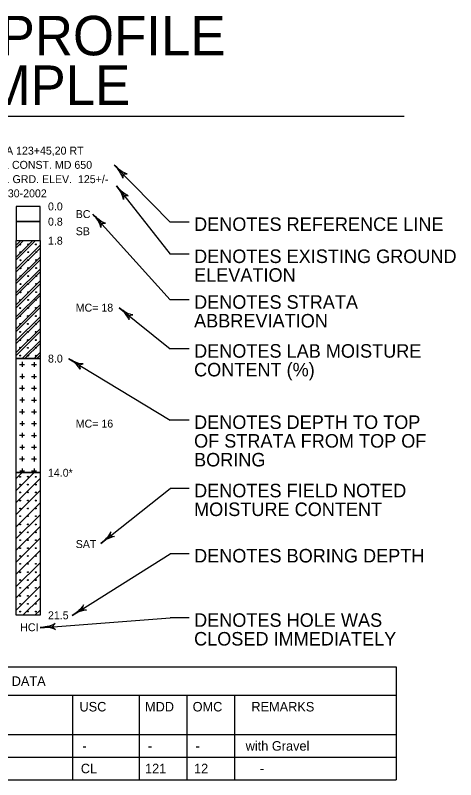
# Model space of a CAD drawing. Extents: x 1.3 to 42.5, y 0 to 21.2.
# Drawn here: x 23.44 to 27.34, y 5.49 to 12.28 of the extents above; entities that cross this region are included whole.
import ezdxf

# ---------------------------------------------------------------- set-up
doc = ezdxf.new("R2010")
doc.units = 0
doc.layers.add('SOIL-BORE', color=7, linetype='Continuous')

msp = doc.modelspace()

# ---------------------------------------------------------------- linework, layer by layer
at = {"layer": 'SOIL-BORE'}
for p, q in [((19.6501, 11.3816), (26.8821, 11.3816)), ((24.3133, 10.9467), (24.8097, 10.4403)), ((24.3135, 10.9469), (24.3135, 10.9469)), ((24.3891, 10.8697), (24.3135, 10.9469)), ((24.3323, 10.9257), (24.3135, 10.9469)), ((24.3351, 10.9265), (24.3135, 10.9469)), ((24.3437, 10.9141), (24.3323, 10.9257)), ((24.3465, 10.9169), (24.3351, 10.9265)), ((24.3577, 10.8957), (24.3437, 10.9141)), ((24.3597, 10.9053), (24.3465, 10.9169)), ((24.3699, 10.8755), (24.3577, 10.8957)), ((24.3701, 10.8967), (24.3597, 10.9053)), ((24.3801, 10.8555), (24.3699, 10.8755)), ((24.3901, 10.8839), (24.3701, 10.8967)), ((24.3859, 10.8421), (24.3801, 10.8555)), ((24.3891, 10.8697), (24.3885, 10.8315)), ((24.3891, 10.8697), (24.4271, 10.8693)), ((24.4045, 10.8771), (24.3901, 10.8839)), ((24.4167, 10.8723), (24.4045, 10.8771)), ((24.4271, 10.8693), (24.4167, 10.8723)), ((24.3885, 10.8315), (24.3859, 10.8421)), ((24.3319, 10.7635), (24.8098, 10.1561)), ((24.3321, 10.7637), (24.3321, 10.7637)), ((24.3989, 10.6787), (24.3321, 10.7637)), ((24.3485, 10.7405), (24.3321, 10.7637)), ((24.3515, 10.7411), (24.3321, 10.7637)), ((24.3585, 10.7279), (24.3485, 10.7405)), ((24.3615, 10.7303), (24.3515, 10.7411)), ((24.3705, 10.7081), (24.3585, 10.7279)), ((24.3737, 10.7173), (24.3615, 10.7303)), ((24.3829, 10.7077), (24.3737, 10.7173)), ((24.3805, 10.6869), (24.3705, 10.7081)), ((24.3885, 10.6655), (24.3805, 10.6869)), ((24.4015, 10.6931), (24.3829, 10.7077)), ((24.3927, 10.6517), (24.3885, 10.6655)), ((24.3943, 10.6409), (24.3927, 10.6517)), ((24.3989, 10.6787), (24.3943, 10.6409)), ((24.3989, 10.6787), (24.4367, 10.6743)), ((24.4147, 10.6847), (24.4015, 10.6931)), ((24.4267, 10.6785), (24.4147, 10.6847)), ((24.4367, 10.6743), (24.4267, 10.6785)), ((24.1239, 10.5119), (24.1239, 10.5119)), ((24.1963, 10.4317), (24.1239, 10.5119)), ((24.1421, 10.4899), (24.1239, 10.5119)), ((24.1451, 10.4907), (24.1239, 10.5119)), ((24.1239, 10.5118), (24.8098, 9.75)), ((24.1529, 10.4779), (24.1421, 10.4899)), ((24.1559, 10.4805), (24.1451, 10.4907)), ((24.1663, 10.4589), (24.1529, 10.4779)), ((24.1685, 10.4683), (24.1559, 10.4805)), ((24.1777, 10.4385), (24.1663, 10.4589)), ((24.1787, 10.4595), (24.1685, 10.4683)), ((24.1979, 10.4459), (24.1787, 10.4595)), ((24.2119, 10.4385), (24.1979, 10.4459)), ((24.1871, 10.4179), (24.1777, 10.4385)), ((24.1919, 10.4041), (24.1871, 10.4179)), ((24.1945, 10.3935), (24.1919, 10.4041)), ((24.1963, 10.4317), (24.1945, 10.3935)), ((24.1963, 10.4317), (24.2343, 10.4297)), ((24.2241, 10.4331), (24.2119, 10.4385)), ((24.2343, 10.4297), (24.2241, 10.4331)), ((24.9785, 10.4403), (24.8098, 10.4403)), ((23.5075, 10.276), (23.4439, 10.2124)), ((23.4842, 10.276), (23.4439, 10.2357)), ((23.591, 10.276), (23.4439, 10.1288)), ((23.6157, 10.276), (23.4439, 10.1042)), ((23.6549, 10.2357), (23.4439, 10.0247)), ((23.6549, 10.2097), (23.4439, 9.9987)), ((23.6549, 10.1289), (23.4439, 9.9179)), ((24.9785, 10.1561), (24.8098, 10.1561)), ((23.6549, 10.1056), (23.4439, 9.8946)), ((23.6549, 10.022), (23.4446, 9.8117)), ((23.6549, 10.0001), (23.446, 9.7911)), ((23.6549, 9.9179), (23.4439, 9.7069)), ((23.6549, 9.8919), (23.4439, 9.6808)), ((23.6549, 9.811), (23.4439, 9.6)), ((23.6549, 9.7877), (23.4439, 9.5767)), ((23.6549, 9.7055), (23.4439, 9.4945)), ((24.9785, 9.75), (24.8098, 9.75)), ((23.6549, 9.6822), (23.4439, 9.4712)), ((24.3553, 9.6803), (24.3553, 9.6803)), ((24.4399, 9.6127), (24.3553, 9.6803)), ((24.3767, 9.6617), (24.3553, 9.6803)), ((24.3793, 9.6627), (24.3553, 9.6803)), ((24.3553, 9.6802), (24.8098, 9.3161)), ((24.3893, 9.6513), (24.3767, 9.6617)), ((24.3917, 9.6547), (24.3793, 9.6627)), ((24.4055, 9.6349), (24.3893, 9.6513)), ((24.4063, 9.6447), (24.3917, 9.6547)), ((24.4201, 9.6165), (24.4055, 9.6349)), ((24.4177, 9.6373), (24.4063, 9.6447)), ((24.4391, 9.6271), (24.4177, 9.6373)), ((23.6549, 9.6), (23.4439, 9.389)), ((23.6549, 9.574), (23.4439, 9.363)), ((24.4329, 9.5977), (24.4201, 9.6165)), ((24.4399, 9.5849), (24.4329, 9.5977)), ((24.4541, 9.6223), (24.4391, 9.6271)), ((24.4399, 9.6127), (24.4777, 9.6171)), ((24.4399, 9.6127), (24.4439, 9.5749)), ((24.4439, 9.5749), (24.4399, 9.5849)), ((24.4669, 9.6187), (24.4541, 9.6223)), ((24.4777, 9.6171), (24.4669, 9.6187)), ((23.6549, 9.4932), (23.4439, 9.2822)), ((23.6549, 9.4685), (23.4439, 9.2575)), ((23.6549, 9.3877), (23.497, 9.2297)), ((23.6549, 9.3644), (23.5203, 9.2297)), ((24.9785, 9.3161), (24.8098, 9.3161)), ((23.6549, 9.2822), (23.6025, 9.2297)), ((23.6549, 9.2589), (23.6257, 9.2297)), ((23.909, 9.2284), (24.8098, 8.684)), ((23.9091, 9.2285), (23.9091, 9.2285)), ((24.0017, 9.1727), (23.9091, 9.2285)), ((23.9327, 9.2129), (23.9091, 9.2285)), ((23.9353, 9.2145), (23.9091, 9.2285)), ((23.4739, 9.1772), (23.5167, 9.1772)), ((23.4953, 9.1983), (23.4953, 9.1561)), ((23.496, 9.1991), (23.496, 9.1569)), ((23.5808, 9.1765), (23.6237, 9.1765)), ((23.6022, 9.1976), (23.6022, 9.1554)), ((23.9465, 9.2045), (23.9327, 9.2129)), ((23.9487, 9.2077), (23.9353, 9.2145)), ((23.9649, 9.1903), (23.9465, 9.2045)), ((23.9643, 9.1999), (23.9487, 9.2077)), ((23.9765, 9.1939), (23.9643, 9.1999)), ((23.9817, 9.1737), (23.9649, 9.1903)), ((23.9989, 9.1869), (23.9765, 9.1939)), ((23.9965, 9.1567), (23.9817, 9.1737)), ((24.0147, 9.1837), (23.9989, 9.1869)), ((24.0017, 9.1727), (24.0387, 9.1819)), ((24.0017, 9.1727), (24.0109, 9.1357)), ((24.0279, 9.1821), (24.0147, 9.1837)), ((24.0387, 9.1819), (24.0279, 9.1821)), ((23.4968, 9.0928), (23.4968, 9.0506)), ((23.6022, 9.0921), (23.6022, 9.0499)), ((24.0055, 9.1451), (23.9965, 9.1567)), ((24.0109, 9.1357), (24.0055, 9.1451)), ((23.4754, 9.0717), (23.5182, 9.0717)), ((23.5808, 9.071), (23.6237, 9.071)), ((23.4739, 8.9678), (23.5167, 8.9678)), ((23.4953, 8.9889), (23.4953, 8.9467)), ((23.496, 8.9896), (23.496, 8.9474)), ((23.5808, 8.967), (23.6237, 8.967)), ((23.6022, 8.9881), (23.6022, 8.9459)), ((23.4754, 8.8623), (23.5182, 8.8623)), ((23.4968, 8.8834), (23.4968, 8.8412)), ((23.5808, 8.8616), (23.6237, 8.8616)), ((23.6022, 8.8827), (23.6022, 8.8405)), ((23.4739, 8.7583), (23.5167, 8.7583)), ((23.4953, 8.7794), (23.4953, 8.7372)), ((23.496, 8.7802), (23.496, 8.738)), ((23.5808, 8.7576), (23.6237, 8.7576)), ((23.6022, 8.7787), (23.6022, 8.7365)), ((24.9785, 8.684), (24.8098, 8.684)), ((23.4754, 8.6529), (23.5182, 8.6529)), ((23.4968, 8.674), (23.4968, 8.6318)), ((23.5808, 8.6521), (23.6237, 8.6521)), ((23.6022, 8.6732), (23.6022, 8.631)), ((23.4739, 8.5489), (23.5167, 8.5489)), ((23.4953, 8.57), (23.4953, 8.5278)), ((23.496, 8.5707), (23.496, 8.5285)), ((23.5808, 8.5481), (23.6237, 8.5481)), ((23.6022, 8.5692), (23.6022, 8.527)), ((23.4754, 8.4434), (23.5182, 8.4434)), ((23.4968, 8.4645), (23.4968, 8.4223)), ((23.5808, 8.4427), (23.6237, 8.4427)), ((23.6022, 8.4638), (23.6022, 8.4216)), ((23.4953, 8.3606), (23.4953, 8.3184)), ((23.496, 8.3613), (23.496, 8.3191)), ((23.6022, 8.3598), (23.6022, 8.3176)), ((23.4739, 8.3395), (23.5167, 8.3395)), ((23.5808, 8.3387), (23.6237, 8.3387)), ((23.4439, 8.0585), (23.6026, 8.2172)), ((23.4439, 8.165), (23.4962, 8.2172)), ((23.4754, 8.234), (23.5182, 8.234)), ((23.4968, 8.2551), (23.4968, 8.2129)), ((23.5808, 8.2332), (23.6237, 8.2332)), ((23.6022, 8.2543), (23.6022, 8.2121)), ((23.4439, 7.953), (23.6549, 8.164)), ((24.193, 7.588), (24.8098, 8.0767)), ((24.9785, 8.0767), (24.8098, 8.0767)), ((23.4439, 7.8465), (23.6549, 8.0575)), ((23.4439, 7.7379), (23.6549, 7.9489)), ((23.4439, 7.6334), (23.6549, 7.8444)), ((23.4439, 7.5289), (23.6549, 7.7399)), ((24.2719, 7.6711), (24.2635, 7.6577)), ((24.2781, 7.6831), (24.2719, 7.6711)), ((24.2779, 7.6553), (24.2821, 7.6931)), ((24.2821, 7.6931), (24.2781, 7.6831)), ((23.4439, 7.4244), (23.6549, 7.6354)), ((24.2779, 7.6553), (24.1931, 7.5881)), ((24.2155, 7.6077), (24.1931, 7.5881)), ((24.2163, 7.6047), (24.1931, 7.5881)), ((24.2263, 7.6179), (24.2155, 7.6077)), ((24.2289, 7.6147), (24.2163, 7.6047)), ((24.2393, 7.6299), (24.2263, 7.6179)), ((24.2487, 7.6269), (24.2289, 7.6147)), ((24.2489, 7.6393), (24.2393, 7.6299)), ((24.2701, 7.6369), (24.2487, 7.6269)), ((24.2635, 7.6577), (24.2489, 7.6393)), ((24.2911, 7.6449), (24.2701, 7.6369)), ((24.2779, 7.6553), (24.3157, 7.6507)), ((24.3049, 7.6491), (24.2911, 7.6449)), ((24.3157, 7.6507), (24.3049, 7.6491)), ((24.1931, 7.5881), (24.1931, 7.5881)), ((23.4439, 7.3159), (23.6549, 7.5269)), ((23.9394, 6.9484), (24.8098, 7.4983)), ((24.9785, 7.4983), (24.8098, 7.4983)), ((23.4439, 7.2073), (23.6549, 7.4183)), ((23.4439, 7.1068), (23.6549, 7.3179)), ((23.4439, 6.9983), (23.6549, 7.2093)), ((23.5017, 6.9516), (23.6549, 7.1048)), ((23.6102, 6.9516), (23.6549, 6.9963)), ((24.0309, 7.0061), (23.9395, 6.9487)), ((24.0005, 6.9935), (23.9897, 6.9851)), ((24.0211, 6.9889), (23.9987, 6.9811)), ((24.0171, 7.0103), (24.0005, 6.9935)), ((24.0267, 7.0229), (24.0171, 7.0103)), ((24.0429, 6.9945), (24.0211, 6.9889)), ((24.0341, 7.0339), (24.0267, 7.0229)), ((24.0309, 7.0061), (24.0391, 7.0435)), ((24.0309, 7.0061), (24.0681, 6.9979)), ((24.0391, 7.0435), (24.0341, 7.0339)), ((24.0573, 6.9973), (24.0429, 6.9945)), ((24.0681, 6.9979), (24.0573, 6.9973)), ((23.6554, 6.8418), (24.8098, 6.9281)), ((23.9639, 6.9657), (23.9395, 6.9487)), ((23.9641, 6.9625), (23.9395, 6.9487)), ((23.9395, 6.9487), (23.9395, 6.9487)), ((23.9757, 6.9745), (23.9639, 6.9657)), ((23.9779, 6.9711), (23.9641, 6.9625)), ((23.9897, 6.9851), (23.9757, 6.9745)), ((23.9987, 6.9811), (23.9779, 6.9711)), ((24.9785, 6.9281), (24.8098, 6.9281)), ((23.7171, 6.8507), (23.6997, 6.8479)), ((23.7305, 6.8531), (23.7171, 6.8507)), ((23.7529, 6.8601), (23.7305, 6.8531)), ((23.7673, 6.8665), (23.7529, 6.8601)), ((23.7633, 6.8501), (23.7881, 6.8791)), ((23.7791, 6.8727), (23.7673, 6.8665)), ((23.7881, 6.8791), (23.7791, 6.8727)), ((23.7633, 6.8501), (23.6555, 6.8421)), ((23.6849, 6.8455), (23.6555, 6.8421)), ((23.6839, 6.8429), (23.6555, 6.8421)), ((23.6555, 6.8421), (23.6555, 6.8421)), ((23.7001, 6.8439), (23.6839, 6.8429)), ((23.6997, 6.8479), (23.6849, 6.8455)), ((23.7231, 6.8429), (23.7001, 6.8439)), ((23.7465, 6.8393), (23.7231, 6.8429)), ((23.7683, 6.8341), (23.7465, 6.8393)), ((23.7633, 6.8501), (23.7921, 6.8251)), ((23.7825, 6.8299), (23.7683, 6.8341)), ((23.7921, 6.8251), (23.7825, 6.8299)), ((19.8937, 6.4947), (26.8125, 6.4947)), ((26.8125, 6.4947), (26.8125, 6.2416)), ((19.8937, 6.2416), (26.8125, 6.2416)), ((23.9437, 6.2416), (23.9437, 6.0412)), ((24.5343, 6.2416), (24.5343, 6.0412)), ((24.9562, 6.2416), (24.9562, 6.0412)), ((25.3781, 6.2416), (25.3781, 6.0412)), ((26.8125, 6.2416), (26.8125, 6.0412)), ((23.9437, 6.0939), (23.9437, 5.8935)), ((24.5343, 6.0939), (24.5343, 5.8935)), ((24.9562, 6.0939), (24.9562, 5.8935)), ((25.3781, 6.0939), (25.3781, 5.8935)), ((26.8125, 6.0939), (26.8125, 5.8935)), ((19.8937, 5.8935), (26.8125, 5.8935)), ((23.9437, 5.8935), (23.9437, 5.6931)), ((24.5343, 5.8935), (24.5343, 5.6931)), ((24.9562, 5.8935), (24.9562, 5.6931)), ((25.3781, 5.8935), (25.3781, 5.6931)), ((26.8125, 5.8935), (26.8125, 5.6931)), ((19.8937, 5.6931), (26.8125, 5.6931)), ((23.9437, 5.6931), (23.9437, 5.4927)), ((24.5343, 5.6931), (24.5343, 5.4927)), ((24.9562, 5.6931), (24.9562, 5.4927)), ((25.3781, 5.6931), (25.3781, 5.4927)), ((26.8125, 5.6931), (26.8125, 5.4927)), ((19.8937, 5.4927), (26.8125, 5.4927))]:
    msp.add_line(p, q, dxfattribs=at)
for points in [[(23.4439, 10.5797), (23.4439, 10.4447), (23.6549, 10.4447), (23.6549, 10.5797)], [(23.4439, 10.4447), (23.4439, 10.276), (23.6549, 10.276), (23.6549, 10.4447)], [(23.4439, 10.276), (23.6549, 10.276), (23.6549, 9.2297), (23.4439, 9.2297)], [(23.4439, 9.2297), (23.6549, 9.2297), (23.6549, 8.2172), (23.4439, 8.2172)], [(23.4439, 8.2172), (23.6549, 8.2172), (23.6549, 6.9516), (23.4439, 6.9516)]]:
    msp.add_lwpolyline(points, close=True, dxfattribs=at)
for centre, radius in [((23.4794, 10.2407), 0.00429), ((23.5493, 10.2421), 0.00429), ((23.6191, 10.2421), 0.00429), ((23.4808, 10.1722), 0.00429), ((23.5506, 10.1736), 0.00429), ((23.6205, 10.1736), 0.00429), ((23.4808, 10.1024), 0.00429), ((23.5506, 10.1037), 0.00429), ((23.6205, 10.1037), 0.00429), ((23.4808, 10.0311), 0.00429), ((23.5506, 10.0325), 0.00429), ((23.6205, 10.0325), 0.00429), ((23.4808, 9.9599), 0.00429), ((23.5506, 9.9612), 0.00429), ((23.6205, 9.9612), 0.00429), ((23.4808, 9.89), 0.00429), ((23.5506, 9.8914), 0.00429), ((23.6205, 9.8914), 0.00429), ((23.4808, 9.8174), 0.00429), ((23.5506, 9.8188), 0.00429), ((23.6205, 9.8188), 0.00429), ((23.4794, 9.7489), 0.00429), ((23.5493, 9.7503), 0.00429), ((23.6191, 9.7503), 0.00429), ((23.4794, 9.6776), 0.00429), ((23.5493, 9.679), 0.00429), ((23.6191, 9.679), 0.00429), ((23.4794, 9.6064), 0.00429), ((23.5479, 9.6064), 0.00429), ((23.6191, 9.6064), 0.00429), ((23.4794, 9.5365), 0.00429), ((23.5479, 9.5365), 0.00429), ((23.6177, 9.5351), 0.00429), ((23.478, 9.4666), 0.00429), ((23.5479, 9.4666), 0.00429), ((23.6177, 9.4666), 0.00429), ((23.4794, 9.394), 0.00429), ((23.5479, 9.394), 0.00429), ((23.6177, 9.394), 0.00429), ((23.4794, 9.3255), 0.00429), ((23.5481, 9.3247), 0.00429), ((23.6176, 9.3247), 0.00429), ((23.4794, 9.2556), 0.00429), ((23.5485, 9.2555), 0.00429), ((23.6176, 9.2551), 0.00429), ((23.4782, 8.1808), 0.00373), ((23.5476, 8.1816), 0.00373), ((23.617, 8.1808), 0.00373), ((23.4782, 8.1114), 0.00373), ((23.5476, 8.1114), 0.00373), ((23.617, 8.1114), 0.00373), ((23.4782, 8.042), 0.00373), ((23.5476, 8.0428), 0.00373), ((23.6177, 8.042), 0.00373), ((23.4784, 7.9693), 0.00373), ((23.5478, 7.97), 0.00373), ((23.6172, 7.9693), 0.00373), ((23.4784, 7.8999), 0.00373), ((23.5478, 7.8999), 0.00373), ((23.6172, 7.8999), 0.00373), ((23.4784, 7.8305), 0.00373), ((23.5478, 7.8312), 0.00373), ((23.6179, 7.8305), 0.00373), ((23.4784, 7.7574), 0.00373), ((23.5478, 7.7581), 0.00373), ((23.6172, 7.7574), 0.00373), ((23.4784, 7.688), 0.00373), ((23.5478, 7.688), 0.00373), ((23.6172, 7.688), 0.00373), ((23.4784, 7.6186), 0.00373), ((23.5478, 7.6193), 0.00373), ((23.6179, 7.6186), 0.00373), ((23.4784, 7.5469), 0.00373), ((23.5478, 7.5477), 0.00373), ((23.6172, 7.5469), 0.00373), ((23.4784, 7.4775), 0.00373), ((23.5478, 7.4775), 0.00373), ((23.6172, 7.4775), 0.00373), ((23.4784, 7.4082), 0.00373), ((23.5478, 7.4089), 0.00373), ((23.6179, 7.4082), 0.00373), ((23.4784, 7.3335), 0.00373), ((23.5478, 7.3343), 0.00373), ((23.6172, 7.3335), 0.00373), ((23.4784, 7.2641), 0.00373), ((23.5478, 7.2641), 0.00373), ((23.6172, 7.2641), 0.00373), ((23.4784, 7.1947), 0.00373), ((23.5478, 7.1955), 0.00373), ((23.6179, 7.1947), 0.00373), ((23.4784, 7.1231), 0.00373), ((23.5478, 7.1239), 0.00373), ((23.6171, 7.1231), 0.00373), ((23.4784, 7.0537), 0.00373), ((23.5478, 7.0537), 0.00373), ((23.6171, 7.0537), 0.00373), ((23.4784, 6.9843), 0.00373), ((23.5478, 6.9851), 0.00373), ((23.6179, 6.9843), 0.00373)]:
    msp.add_circle(centre, radius, dxfattribs=at)

# ---------------------------------------------------------------- texts
for s, height, p in [('SOIL BORING PROFILE', 0.35, (20.1241, 11.9203)), ('EXAMPLE', 0.35, (22.2443, 11.4803)), ('STA 123+45,20 RT', 0.070308, (23.2337, 11.0393)), ('C/L CONST. MD 650', 0.070308, (23.2337, 10.9133)), ('EX. GRD. ELEV.  125+/-', 0.070308, (23.2337, 10.7863)), ('09-30-2002', 0.07031, (23.2337, 10.6603)), ('0.0', 0.07031, (23.7257, 10.5443)), ('BC', 0.07031, (23.9717, 10.4763)), ('0.8', 0.07031, (23.7257, 10.4093)), ('DENOTES REFERENCE LINE', 0.12, (25.0207, 10.3623)), ('SB', 0.07031, (23.9717, 10.3243)), ('1.8', 0.07031, (23.7257, 10.2403)), ('DENOTES EXISTING GROUND', 0.12, (25.0207, 10.0773)), ('ELEVATION', 0.12, (25.0207, 9.9113)), ('DENOTES STRATA', 0.12, (25.0207, 9.6713)), ('MC= 18', 0.07031, (23.9717, 9.6463)), ('ABBREVIATION', 0.12, (25.0207, 9.5053)), ('DENOTES LAB MOISTURE', 0.12, (25.0207, 9.2373)), ('8.0', 0.07031, (23.7257, 9.1943)), ('CONTENT (%)', 0.12, (25.0207, 9.0713)), ('MC= 16', 0.07031, (23.9717, 8.6173)), ('DENOTES DEPTH TO TOP', 0.12, (25.0207, 8.6053)), ('OF STRATA FROM TOP OF', 0.12, (25.0207, 8.4393)), ('BORING', 0.12, (25.0207, 8.2723)), ('14.0*', 0.07031, (23.7257, 8.1813)), ('DENOTES FIELD NOTED', 0.12, (25.0207, 7.9983)), ('MOISTURE CONTENT', 0.12, (25.0207, 7.8323)), ('SAT', 0.07031, (23.9717, 7.5483)), ('DENOTES BORING DEPTH', 0.12, (25.0207, 7.4203)), ('21.5', 0.07031, (23.7257, 6.9163)), ('DENOTES HOLE WAS', 0.12, (25.0207, 6.8493)), ('HCI', 0.07031, (23.4797, 6.8103)), ('CLOSED IMMEDIATELY', 0.12, (25.0207, 6.6833)), ('SOILS TEST DATA', 0.08437, (22.7208, 6.3251)), ('USC', 0.08437, (24.0048, 6.0983)), (' MDD', 0.08437, (24.5544, 6.0983)), (' OMC', 0.08437, (24.9768, 6.0983)), ('REMARKS', 0.08437, (25.5288, 6.0983)), ('with Gravel', 0.08437, (25.4784, 5.7503)), ('-', 0.0844, (24.03, 5.7503)), (' -', 0.08437, (24.5796, 5.7503)), (' -', 0.08437, (25.002, 5.7503)), ('CL', 0.08437, (24.0168, 5.5499)), (' 121', 0.08437, (24.5544, 5.5499)), (' 12', 0.08437, (24.9888, 5.5499)), ('-', 0.0844, (25.6044, 5.5499))]:
    msp.add_text(s, height=height, dxfattribs=at).set_placement(p)

doc.saveas('drawing.dxf')
